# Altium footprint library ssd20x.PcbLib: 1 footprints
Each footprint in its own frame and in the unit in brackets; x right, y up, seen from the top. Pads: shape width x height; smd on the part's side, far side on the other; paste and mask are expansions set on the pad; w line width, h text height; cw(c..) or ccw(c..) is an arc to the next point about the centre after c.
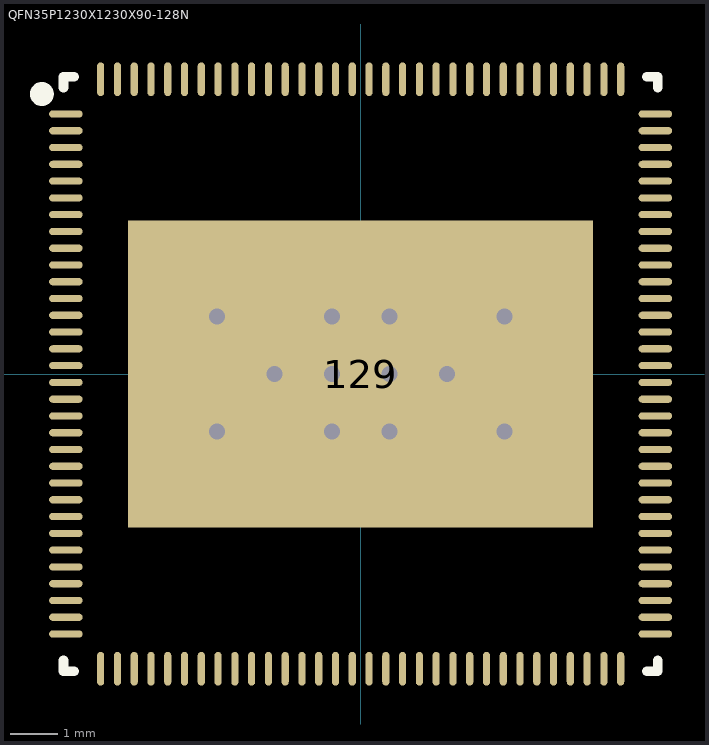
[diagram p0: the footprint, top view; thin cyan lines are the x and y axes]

## QFN35P1230X1230X90-128N [mm] "QFN, 128-Leads, Body 12.4x12.4mm (max), Pitch 0.35mm, IPC Medium Density"
height 0.9
pads (129):
  oval 0.7x0.15 smd: 1(-6.15,5.425) 2(-6.15,5.075) 3(-6.15,4.725) 4(-6.15,4.375) 5(-6.15,4.025) 6(-6.15,3.675) 7(-6.15,3.325) 8(-6.15,2.975) 9(-6.15,2.625) 10(-6.15,2.275) 11(-6.15,1.925) 12(-6.15,1.575) 13(-6.15,1.225) 14(-6.15,0.875) 15(-6.15,0.525) 16(-6.15,0.175) 17(-6.15,-0.175) 18(-6.15,-0.525) 19(-6.15,-0.875) 20(-6.15,-1.225) 21(-6.15,-1.575) 22(-6.15,-1.925) 23(-6.15,-2.275) 24(-6.15,-2.625) 25(-6.15,-2.975) 26(-6.15,-3.325) 27(-6.15,-3.675) 28(-6.15,-4.025) 29(-6.15,-4.375) 30(-6.15,-4.725) 31(-6.15,-5.075) 32(-6.15,-5.425) 65(6.15,-5.425) 66(6.15,-5.075) 67(6.15,-4.725) 68(6.15,-4.375) 69(6.15,-4.025) 70(6.15,-3.675) 71(6.15,-3.325) 72(6.15,-2.975) 73(6.15,-2.625) 74(6.15,-2.275) 75(6.15,-1.925) 76(6.15,-1.575) 77(6.15,-1.225) 78(6.15,-0.875) 79(6.15,-0.525) 80(6.15,-0.175) 81(6.15,0.175) 82(6.15,0.525) 83(6.15,0.875) 84(6.15,1.225) 85(6.15,1.575) 86(6.15,1.925) 87(6.15,2.275) 88(6.15,2.625) 89(6.15,2.975) 90(6.15,3.325) 91(6.15,3.675) 92(6.15,4.025) 93(6.15,4.375) 94(6.15,4.725) 95(6.15,5.075) 96(6.15,5.425)
  oval 0.15x0.7 smd: 33(-5.425,-6.15) 34(-5.075,-6.15) 35(-4.725,-6.15) 36(-4.375,-6.15) 37(-4.025,-6.15) 38(-3.675,-6.15) 39(-3.325,-6.15) 40(-2.975,-6.15) 41(-2.625,-6.15) 42(-2.275,-6.15) 43(-1.925,-6.15) 44(-1.575,-6.15) 45(-1.225,-6.15) 46(-0.875,-6.15) 47(-0.525,-6.15) 48(-0.175,-6.15) 49(0.175,-6.15) 50(0.525,-6.15) 51(0.875,-6.15) 52(1.225,-6.15) 53(1.575,-6.15) 54(1.925,-6.15) 55(2.275,-6.15) 56(2.625,-6.15) 57(2.975,-6.15) 58(3.325,-6.15) 59(3.675,-6.15) 60(4.025,-6.15) 61(4.375,-6.15) 62(4.725,-6.15) 63(5.075,-6.15) 64(5.425,-6.15) 97(5.425,6.15) 98(5.075,6.15) 99(4.725,6.15) 100(4.375,6.15) 101(4.025,6.15) 102(3.675,6.15) 103(3.325,6.15) 104(2.975,6.15) 105(2.625,6.15) 106(2.275,6.15) 107(1.925,6.15) 108(1.575,6.15) 109(1.225,6.15) 110(0.875,6.15) 111(0.525,6.15) 112(0.175,6.15) 113(-0.175,6.15) 114(-0.525,6.15) 115(-0.875,6.15) 116(-1.225,6.15) 117(-1.575,6.15) 118(-1.925,6.15) 119(-2.275,6.15) 120(-2.625,6.15) 121(-2.975,6.15) 122(-3.325,6.15) 123(-3.675,6.15) 124(-4.025,6.15) 125(-4.375,6.15) 126(-4.725,6.15) 127(-5.075,6.15) 128(-5.425,6.15)
  rect 9.7x6.4 smd: 129(0,0)
via -1.8,0 diameter 0.66 hole 0.33
via 1.8,0 diameter 0.66 hole 0.33
via -3,1.2 diameter 0.66 hole 0.33
via -0.6,1.2 diameter 0.66 hole 0.33
via 0.6,1.2 diameter 0.66 hole 0.33
via 3,1.2 diameter 0.66 hole 0.33
via -0.6,0 diameter 0.66 hole 0.33
via 0.6,0 diameter 0.66 hole 0.33
via -3,-1.2 diameter 0.66 hole 0.33
via -0.6,-1.2 diameter 0.66 hole 0.33
via 0.6,-1.2 diameter 0.66 hole 0.33
via 3,-1.2 diameter 0.66 hole 0.33
Top Overlay:
  circle w0.25: c-6.653,5.842 r0.125
  lines w0.2: -6.2,-5.975 -6.2,-6.2 -5.975,-6.2 ; -6.2,5.975 -6.2,6.2 -5.975,6.2 ; 5.975,-6.2 6.2,-6.2 6.2,-5.975 ; 5.975,6.2 6.2,6.2 6.2,5.975
3D body: height 0.9, standoff 0.01, extent -6.2,-6.2 6.2,6.2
